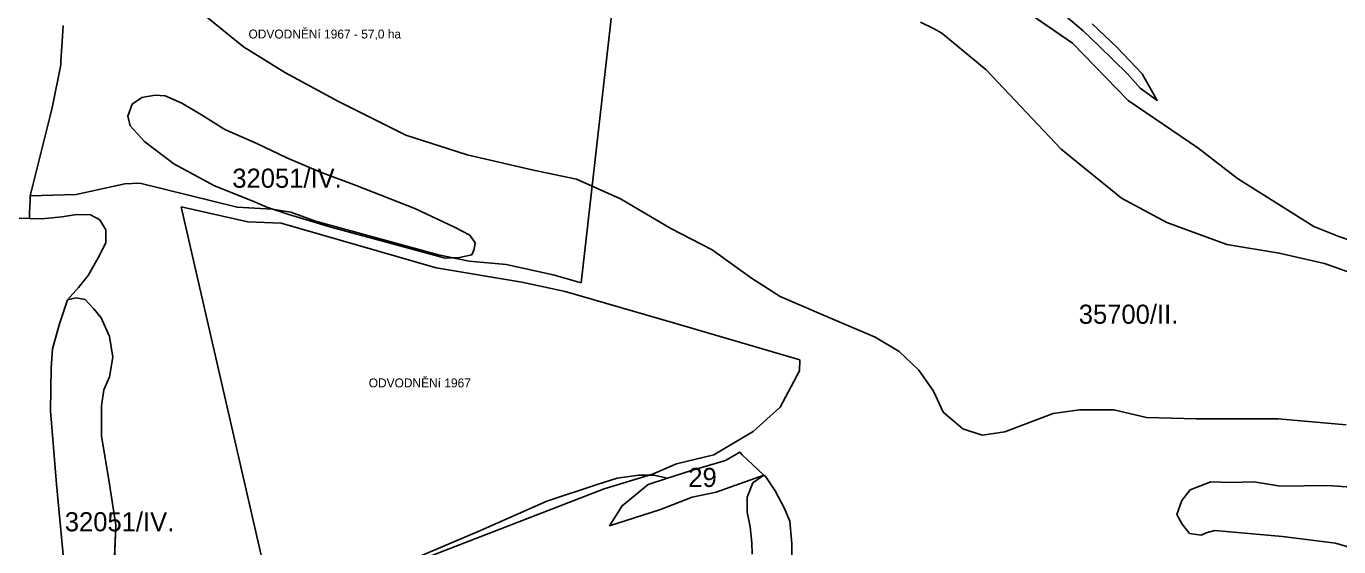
# Model space of a CAD drawing. Extents: x -521621 to -516761, y -1190184 to -1184927.
# Drawn here: x -520715 to -519686, y -1187419 to -1187011 of the extents above; entities that cross this region are included whole.
import ezdxf

# ---------------------------------------------------------------- set-up
doc = ezdxf.new("R2010")
doc.units = 0
doc.layers.add('BPEJ_s', color=7, linetype='Continuous')
doc.layers.add('odvodneni_s', color=7, linetype='Continuous')

msp = doc.modelspace()

# ---------------------------------------------------------------- linework, layer by layer
at = {"layer": 'BPEJ_s'}
for p, q in [((-519894.5, -1187024.1), (-519975.4, -1186968.4)), ((-520594.8, -1186986.3), (-520544.7, -1187027.1)), ((-519915.9, -1186989.2), (-519886.2, -1187014.6)), ((-519859.4, -1187027.5), (-519879.1, -1187008.9)), ((-520687.1, -1187022.9), (-520686.3, -1187010.2)), ((-519886.2, -1187014.6), (-519873.7, -1187026.4)), ((-520688, -1187037.9), (-520687.1, -1187022.9)), ((-520544.7, -1187027.1), (-520512, -1187047.5)), ((-519850.9, -1187069.2), (-519894.5, -1187024.1)), ((-519873.7, -1187026.4), (-519851.5, -1187048.2)), ((-519839.8, -1187048.2), (-519859.4, -1187027.5)), ((-520688.2, -1187041), (-520688, -1187037.9)), ((-520694.7, -1187073.5), (-520688.3, -1187042.5)), ((-520688.3, -1187042.5), (-520688.2, -1187041)), ((-520512, -1187047.5), (-520470.3, -1187069.8)), ((-519851.5, -1187048.2), (-519841.5, -1187059.6)), ((-519828, -1187069.1), (-519839.8, -1187048.2)), ((-519841.5, -1187059.6), (-519828, -1187069.1)), ((-520624.7, -1187066.8), (-520632.2, -1187072)), ((-520614.2, -1187064.9), (-520624.7, -1187066.8)), ((-520606.4, -1187065.6), (-520614.2, -1187064.9)), ((-520593.2, -1187071.3), (-520606.4, -1187065.6)), ((-520470.3, -1187069.8), (-520417.4, -1187096.4)), ((-519796.1, -1187106.2), (-519850.9, -1187069.2)), ((-520696.6, -1187081.2), (-520694.7, -1187073.5)), ((-520632.2, -1187072), (-520635.6, -1187081.4)), ((-520577.9, -1187080.3), (-520593.2, -1187071.3)), ((-520559.5, -1187091.9), (-520577.9, -1187080.3)), ((-520712.1, -1187143.9), (-520696.6, -1187081.2)), ((-520635.6, -1187081.4), (-520633.7, -1187088.9)), ((-520633.7, -1187088.9), (-520622.1, -1187101.6)), ((-520622.1, -1187101.6), (-520599.6, -1187118.9)), ((-520534.4, -1187102.8), (-520559.5, -1187091.9)), ((-520417.4, -1187096.4), (-520369.4, -1187111.8)), ((-520510.8, -1187114), (-520534.4, -1187102.8)), ((-520369.4, -1187111.8), (-520317.3, -1187123.8)), ((-519765.2, -1187130.4), (-519796.1, -1187106.2)), ((-520599.6, -1187118.9), (-520567.7, -1187136.2)), ((-520484.5, -1187125.3), (-520510.8, -1187114)), ((-520456.4, -1187135.8), (-520484.5, -1187125.3)), ((-520317.3, -1187123.8), (-520283.6, -1187130.9)), ((-520283.6, -1187130.9), (-520249.1, -1187146.3)), ((-519705.2, -1187168.1), (-519765.2, -1187130.4)), ((-520567.7, -1187136.2), (-520538.1, -1187147.8)), ((-520410.3, -1187153.8), (-520456.4, -1187135.8)), ((-520712.6, -1187156.9), (-520712.4, -1187152.2)), ((-520712.4, -1187150.9), (-520712.3, -1187148.8)), ((-520712.4, -1187152.2), (-520712.4, -1187150.9)), ((-520712.3, -1187148.8), (-520712.1, -1187143.9)), ((-520538.1, -1187147.8), (-520526.5, -1187152.7)), ((-520526.5, -1187152.7), (-520509.3, -1187158.6)), ((-520249.1, -1187146.3), (-520209.7, -1187169.5)), ((-520712.8, -1187161.7), (-520712.7, -1187159.3)), ((-520703.3, -1187162.1), (-520712.8, -1187161.7)), ((-520712.7, -1187159.3), (-520712.6, -1187156.9)), ((-520687.1, -1187160.5), (-520703.3, -1187162.1)), ((-520675.8, -1187158.5), (-520687.1, -1187160.5)), ((-520664.8, -1187158.9), (-520675.8, -1187158.5)), ((-520657.4, -1187162.8), (-520664.8, -1187158.9)), ((-520652.7, -1187170.7), (-520657.4, -1187162.8)), ((-520509.3, -1187158.6), (-520476.4, -1187168.5)), ((-520379.2, -1187168.4), (-520410.3, -1187153.8)), ((-520652.7, -1187180.5), (-520652.7, -1187170.7)), ((-520476.4, -1187168.5), (-520433.7, -1187180)), ((-520367.2, -1187174.8), (-520379.2, -1187168.4)), ((-520209.7, -1187169.5), (-520177.1, -1187186.4)), ((-519685.7, -1187175.9), (-519705.2, -1187168.1)), ((-520657.4, -1187190.3), (-520652.7, -1187180.5)), ((-520433.7, -1187180), (-520386.7, -1187192.9)), ((-520363, -1187180.8), (-520367.2, -1187174.8)), ((-520363.8, -1187185.7), (-520363, -1187180.8)), ((-519667.2, -1187182), (-519685.7, -1187175.9)), ((-520666.8, -1187206.3), (-520657.4, -1187190.3)), ((-520386.7, -1187192.9), (-520375.4, -1187192.4)), ((-520375.4, -1187192.4), (-520365.7, -1187190.2)), ((-520365.7, -1187190.2), (-520363.8, -1187185.7)), ((-520177.1, -1187186.4), (-520146.3, -1187208.6)), ((-520674.2, -1187215.8), (-520666.8, -1187206.3)), ((-520146.3, -1187208.6), (-520123.8, -1187222.8)), ((-520682.9, -1187225.6), (-520674.2, -1187215.8)), ((-520676.2, -1187224), (-520682.9, -1187225.6)), ((-520669.1, -1187225.2), (-520676.2, -1187224)), ((-520662.1, -1187232.6), (-520669.1, -1187225.2)), ((-520123.8, -1187222.8), (-520087.9, -1187238.2)), ((-520656.6, -1187239.7), (-520662.1, -1187232.6)), ((-520649.9, -1187254.2), (-520656.6, -1187239.7)), ((-520087.9, -1187238.2), (-520049.2, -1187254.7)), ((-520647.2, -1187270.6), (-520649.9, -1187254.2)), ((-520049.2, -1187254.7), (-520030.5, -1187266)), ((-520030.5, -1187266), (-520015.1, -1187280.6)), ((-520649.9, -1187285.9), (-520647.2, -1187270.6)), ((-520654.3, -1187296.1), (-520649.9, -1187285.9)), ((-520015.1, -1187280.6), (-520003.5, -1187297.1)), ((-520656.2, -1187308.6), (-520654.3, -1187296.1)), ((-520003.5, -1187297.1), (-519996, -1187313.6)), ((-520656.2, -1187332.2), (-520656.2, -1187308.6)), ((-519996, -1187313.6), (-519980.6, -1187326.7)), ((-519934.5, -1187324.1), (-519909.8, -1187314.7)), ((-519909.8, -1187314.7), (-519889.1, -1187311.7)), ((-519889.1, -1187311.7), (-519862, -1187311.7)), ((-519862, -1187311.7), (-519836.6, -1187317.7)), ((-519836.6, -1187317.7), (-519797.2, -1187318.9)), ((-519980.6, -1187326.7), (-519965.3, -1187331.6)), ((-519947.6, -1187329), (-519934.5, -1187324.1)), ((-519797.2, -1187318.9), (-519733.3, -1187318.9)), ((-519733.3, -1187318.9), (-519679.9, -1187323.6)), ((-520649.9, -1187370.2), (-520656.2, -1187332.2)), ((-519965.3, -1187331.6), (-519947.6, -1187329)), ((-520155.6, -1187344.9), (-520166.6, -1187351.5)), ((-520153.6, -1187347.1), (-520155.6, -1187344.9)), ((-520136.7, -1187363), (-520153.6, -1187347.1)), ((-520166.6, -1187351.5), (-520193.3, -1187359.5)), ((-520251.8, -1187365.3), (-520267.5, -1187370.4)), ((-520234.8, -1187363.1), (-520251.8, -1187365.3)), ((-520223, -1187363.1), (-520234.8, -1187363.1)), ((-520212.1, -1187365.4), (-520223, -1187363.1)), ((-520193.3, -1187359.5), (-520212.1, -1187365.4)), ((-520135.1, -1187364.3), (-520136.7, -1187363)), ((-520127.7, -1187375.4), (-520135.1, -1187364.3)), ((-519786, -1187368.3), (-519802.2, -1187374.5)), ((-519770.3, -1187368.8), (-519786, -1187368.3)), ((-519752.3, -1187368.3), (-519770.3, -1187368.8)), ((-519731.4, -1187371.6), (-519752.3, -1187368.3)), ((-520644.9, -1187402.3), (-520649.9, -1187370.2)), ((-520267.5, -1187370.4), (-520307, -1187383.4)), ((-520120.7, -1187388.6), (-520127.7, -1187375.4)), ((-519802.2, -1187374.5), (-519808.8, -1187383)), ((-519694.3, -1187371.1), (-519731.4, -1187371.6)), ((-519668.7, -1187373), (-519694.3, -1187371.1)), ((-520307, -1187383.4), (-520358.9, -1187406.5)), ((-520116.3, -1187399.2), (-520120.7, -1187388.6)), ((-519808.8, -1187383), (-519812.6, -1187394)), ((-520114.8, -1187416.9), (-520116.3, -1187399.2)), ((-519812.6, -1187394), (-519808.4, -1187401.6)), ((-520646.8, -1187445.4), (-520644.9, -1187402.3)), ((-520358.9, -1187406.5), (-520432.1, -1187437.5)), ((-519808.4, -1187401.6), (-519802.7, -1187408.7)), ((-519802.7, -1187408.7), (-519793.6, -1187410.1)), ((-519793.6, -1187410.1), (-519789.8, -1187408.2)), ((-519789.8, -1187408.2), (-519783, -1187406.4)), ((-519783, -1187406.4), (-519729.9, -1187411.3)), ((-520115, -1187434.6), (-520114.8, -1187416.9)), ((-519729.9, -1187411.3), (-519688.3, -1187416.3)), ((-519688.3, -1187416.3), (-519642.9, -1187429.9))]:
    msp.add_line(p, q, dxfattribs=at)
for points in [[(-520010.6, -1186930.1), (-520009.9, -1186950.2), (-519996.6, -1186972.9), (-519977.6, -1186973.3), (-519975.4, -1186968.4), (-519894.5, -1187024.1), (-519850.9, -1187069.2), (-519796.1, -1187106.2), (-519765.2, -1187130.4), (-519705.2, -1187168.1), (-519685.7, -1187175.9), (-519667.2, -1187182)], [(-519679.9, -1187323.6), (-519733.3, -1187318.9), (-519797.2, -1187318.9), (-519836.6, -1187317.7), (-519862, -1187311.7), (-519889.1, -1187311.7), (-519909.8, -1187314.7), (-519934.5, -1187324.1), (-519947.6, -1187329), (-519965.3, -1187331.6), (-519980.6, -1187326.7), (-519996, -1187313.6), (-520003.5, -1187297.1), (-520015.1, -1187280.6), (-520030.5, -1187266), (-520049.2, -1187254.7), (-520087.9, -1187238.2), (-520123.8, -1187222.8), (-520146.3, -1187208.6), (-520177.1, -1187186.4), (-520209.7, -1187169.5), (-520249.1, -1187146.3), (-520283.6, -1187130.9), (-520317.3, -1187123.8), (-520369.4, -1187111.8), (-520417.4, -1187096.4), (-520470.3, -1187069.8), (-520512, -1187047.5), (-520544.7, -1187027.1), (-520594.8, -1186986.3)], [(-519879.1, -1187008.9), (-519859.4, -1187027.5), (-519839.8, -1187048.2), (-519828, -1187069.1), (-519841.5, -1187059.6), (-519851.5, -1187048.2), (-519873.7, -1187026.4), (-519886.2, -1187014.6), (-519915.9, -1186989.2)], [(-520013.7, -1187007.7), (-520003.6, -1187012.6), (-519997, -1187016.4), (-519962.2, -1187045.1), (-519903.4, -1187107.4), (-519856.2, -1187145.7), (-519820.6, -1187164.9), (-519773.4, -1187182), (-519732.4, -1187188.8), (-519696.8, -1187197), (-519677.1, -1187204.1)], [(-519677.1, -1187204.1), (-519696.8, -1187197), (-519732.4, -1187188.8), (-519773.4, -1187182), (-519820.6, -1187164.9), (-519856.2, -1187145.7), (-519903.4, -1187107.4), (-519962.2, -1187045.1), (-519997, -1187016.4), (-520003.6, -1187012.6), (-520013.7, -1187007.7)], [(-520720.8, -1187161.5), (-520712.8, -1187161.7), (-520703.3, -1187162.1), (-520687.1, -1187160.5), (-520675.8, -1187158.5), (-520664.8, -1187158.9), (-520657.4, -1187162.8), (-520652.7, -1187170.7), (-520652.7, -1187180.5), (-520657.4, -1187190.3), (-520666.8, -1187206.3), (-520674.2, -1187215.8), (-520682.9, -1187225.6), (-520689.1, -1187244.4), (-520694.6, -1187264), (-520695.8, -1187279.2), (-520696.2, -1187312.6), (-520691.5, -1187370.2), (-520684.4, -1187445)], [(-520684.4, -1187445), (-520691.5, -1187370.2), (-520696.2, -1187312.6), (-520695.8, -1187279.2), (-520694.6, -1187264), (-520689.1, -1187244.4), (-520682.9, -1187225.6), (-520676.2, -1187224), (-520669.1, -1187225.2), (-520662.1, -1187232.6), (-520656.6, -1187239.7), (-520649.9, -1187254.2), (-520647.2, -1187270.6), (-520649.9, -1187285.9), (-520654.3, -1187296.1), (-520656.2, -1187308.6), (-520656.2, -1187332.2), (-520649.9, -1187370.2), (-520644.9, -1187402.3), (-520646.8, -1187445.4)], [(-520432.1, -1187437.5), (-520358.9, -1187406.5), (-520307, -1187383.4), (-520267.5, -1187370.4), (-520251.8, -1187365.3), (-520234.8, -1187363.1), (-520223, -1187363.1), (-520212.1, -1187365.4), (-520227.5, -1187370.3), (-520247.9, -1187387.1), (-520257.7, -1187402.8), (-520217.8, -1187390.1), (-520193, -1187380.4), (-520174, -1187376.4), (-520136.7, -1187363), (-520145.2, -1187369.2), (-520149.8, -1187380.2), (-520149.8, -1187392), (-520147.5, -1187403.6), (-520146, -1187416.1), (-520145.8, -1187425.1)], [(-520145.8, -1187425.1), (-520146, -1187416.1), (-520147.5, -1187403.6), (-520149.8, -1187392), (-520149.8, -1187380.2), (-520145.2, -1187369.2), (-520136.7, -1187363), (-520135.1, -1187364.3), (-520127.7, -1187375.4), (-520120.7, -1187388.6), (-520116.3, -1187399.2), (-520114.8, -1187416.9), (-520115, -1187434.6)], [(-519642.9, -1187429.9), (-519688.3, -1187416.3), (-519729.9, -1187411.3), (-519783, -1187406.4), (-519789.8, -1187408.2), (-519793.6, -1187410.1), (-519802.7, -1187408.7), (-519808.4, -1187401.6), (-519812.6, -1187394), (-519808.8, -1187383), (-519802.2, -1187374.5), (-519786, -1187368.3), (-519770.3, -1187368.8), (-519752.3, -1187368.3), (-519731.4, -1187371.6), (-519694.3, -1187371.1), (-519668.7, -1187373)]]:
    msp.add_lwpolyline(points, dxfattribs=at)
for points in [[(-520614.2, -1187064.9), (-520606.4, -1187065.6), (-520593.2, -1187071.3), (-520577.9, -1187080.3), (-520559.5, -1187091.9), (-520534.4, -1187102.8), (-520510.8, -1187114), (-520484.5, -1187125.3), (-520456.4, -1187135.8), (-520410.3, -1187153.8), (-520379.2, -1187168.4), (-520367.2, -1187174.8), (-520363, -1187180.8), (-520363.8, -1187185.7), (-520365.7, -1187190.2), (-520375.4, -1187192.4), (-520386.7, -1187192.9), (-520433.7, -1187180), (-520476.4, -1187168.5), (-520509.3, -1187158.6), (-520526.5, -1187152.7), (-520538.1, -1187147.8), (-520567.7, -1187136.2), (-520599.6, -1187118.9), (-520622.1, -1187101.6), (-520633.7, -1187088.9), (-520635.6, -1187081.4), (-520632.2, -1187072), (-520624.7, -1187066.8)], [(-520212.1, -1187365.4), (-520193.3, -1187359.5), (-520166.6, -1187351.5), (-520155.6, -1187344.9), (-520153.6, -1187347.1), (-520136.7, -1187363), (-520174, -1187376.4), (-520193, -1187380.4), (-520217.8, -1187390.1), (-520257.7, -1187402.8), (-520247.9, -1187387.1), (-520227.5, -1187370.3)]]:
    msp.add_lwpolyline(points, close=True, dxfattribs=at)
at = {"layer": 'odvodneni_s'}
msp.add_lwpolyline([(-520686.3, -1187010.2), (-520687.1, -1187022.9), (-520688, -1187037.9), (-520688.2, -1187041), (-520688.3, -1187042.5), (-520694.7, -1187073.5), (-520696.6, -1187081.2), (-520712.1, -1187143.9), (-520676.2, -1187143), (-520638, -1187134.6), (-520626.1, -1187134.1), (-520549.7, -1187152.9), (-520522.4, -1187154.5), (-520507.8, -1187156.8), (-520488.4, -1187163.7), (-520391.8, -1187190.3), (-520367.9, -1187195.1), (-520338.9, -1187197.9), (-520302, -1187205.9), (-520280, -1187212.1), (-520239.3, -1186854.9)], dxfattribs=at)
msp.add_lwpolyline([(-520593.8, -1187152.6), (-520541.5, -1187164.4), (-520515.4, -1187165.5), (-520393.8, -1187200.4), (-520326.6, -1187211.6), (-520292.6, -1187219), (-520207.5, -1187243.6), (-520108.5, -1187272.6), (-520108.7, -1187281.3), (-520123.8, -1187309.7), (-520145.1, -1187328.8), (-520176, -1187347), (-520205.1, -1187354.1), (-520224.1, -1187362.3), (-520261.9, -1187373.9), (-520520.1, -1187473.8)], close=True, dxfattribs=at)

# ---------------------------------------------------------------- texts
at = {"layer": 'BPEJ_s'}
for s, p in [('32051/IV.', (-520553.6, -1187137.6)), ('35700/II.', (-519889.6, -1187244.3)), ('29', (-520195.9, -1187372.3)), ('32051/IV.', (-520685, -1187407.1))]:
    msp.add_text(s, height=15, dxfattribs=at).set_placement(p)
at = {"layer": 'odvodneni_s'}
for s, p in [('ODVODNĚNí 1967 - 57,0 ha', (-520540.9, -1187020.5)), ('ODVODNĚNí 1967', (-520446.6, -1187294.2))]:
    msp.add_text(s, height=7, dxfattribs=at).set_placement(p)

doc.saveas('drawing.dxf')
